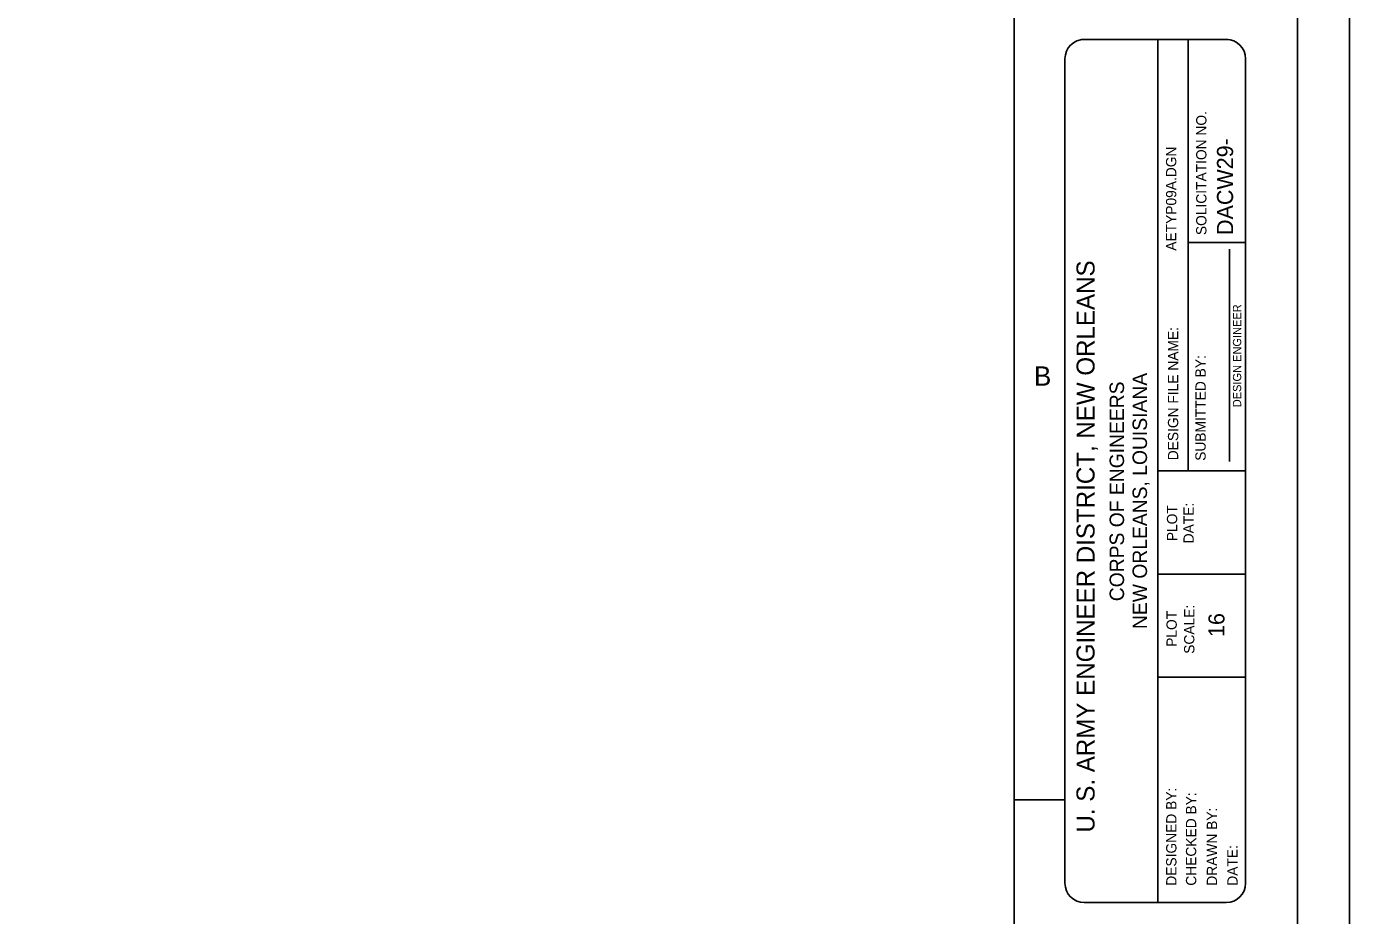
# Model space of a CAD drawing. Extents: x 22369.6 to 22428.3, y 22369.6 to 22415.
# Drawn here: x 22411.18 to 22428.29, y 22379.78 to 22391.29 of the extents above; entities that cross this region are included whole.
import ezdxf

# ---------------------------------------------------------------- set-up
doc = ezdxf.new("R2010")
doc.units = 0
for name, color, linetype in [('Level 1', 7, 'Continuous'), ('Level 10', 7, 'Continuous'), ('Level 2', 7, 'Continuous'), ('Level 7', 7, 'Continuous'), ('Level 9', 7, 'Continuous')]:
    doc.layers.add(name, color=color, linetype=linetype)

msp = doc.modelspace()

# ---------------------------------------------------------------- linework, layer by layer
at = {"layer": 'Level 1'}
for p, q in [((22426.72, 22391.12), (22424.816, 22391.12)), ((22425.808, 22391.12), (22425.808, 22379.952))]:
    msp.add_line(p, q, dxfattribs=at)
msp.add_lwpolyline([(22369.621, 22414.955), (22428.288, 22414.955), (22428.288, 22369.621), (22369.621, 22369.621)], close=True, dxfattribs=at)
for points in [[(22426.694, 22391.12), (22424.858, 22391.12)], [(22424.608, 22380.202), (22424.608, 22390.87)], [(22426.944, 22380.202), (22426.944, 22390.87)], [(22424.858, 22379.952), (22426.694, 22379.952)]]:
    msp.add_lwpolyline(points, dxfattribs=at)
for centre, start, end in [((22424.858, 22390.87), 90, 180), ((22426.694, 22390.87), 0, 90), ((22424.858, 22380.202), 180, 270), ((22426.694, 22380.202), 270, 0)]:
    msp.add_arc(centre, 0.25, start, end, dxfattribs=at)
at = {"layer": 'Level 10'}
msp.add_line((22423.952, 22381.28), (22424.608, 22381.28), dxfattribs=at)
at = {"layer": 'Level 2'}
for p, q in [((22426.202, 22391.12), (22426.202, 22385.536)), ((22426.944, 22388.491), (22426.202, 22388.491)), ((22426.736, 22385.657), (22426.736, 22388.405)), ((22426.944, 22385.536), (22425.808, 22385.536)), ((22426.944, 22384.203), (22425.808, 22384.203)), ((22426.944, 22382.869), (22425.808, 22382.869))]:
    msp.add_line(p, q, dxfattribs=at)
at = {"layer": 'Level 9'}
msp.add_line((22427.616, 22370.288), (22427.616, 22414.288), dxfattribs=at)
msp.add_lwpolyline([(22423.952, 22370.288), (22423.952, 22414.288)], dxfattribs=at)

# ---------------------------------------------------------------- texts
at = {"layer": 'Level 1'}
for s, height, p in [('SOLICITATION NO.', 0.13334, (22426.438, 22388.588)), ('AETYP09A.DGN', 0.13334, (22426.048, 22388.386)), ('U. S. ARMY ENGINEER DISTRICT, NEW ORLEANS', 0.23333, (22424.991, 22380.858)), ('DESIGN ENGINEER', 0.10666, (22426.887, 22386.361)), ('DESIGN FILE NAME:', 0.13334, (22426.073, 22385.675)), ('SUBMITTED BY:', 0.13334, (22426.428, 22385.668)), ('PLOT', 0.1333, (22426.06, 22384.628)), ('DATE:', 0.1333, (22426.273, 22384.6)), ('PLOT', 0.1333, (22426.054, 22383.261)), ('SCALE:', 0.1333, (22426.282, 22383.171)), ('DESIGNED BY:', 0.13334, (22426.05, 22380.17)), ('CHECKED BY:', 0.13334, (22426.306, 22380.17)), ('DRAWN BY:', 0.1333, (22426.575, 22380.17)), ('DATE:', 0.1333, (22426.841, 22380.17))]:
    msp.add_text(s, height=height, rotation=90, dxfattribs=at).set_placement(p)
msp.add_text('B', height=0.25, dxfattribs=at).set_placement((22424.208, 22386.64))
at = {"layer": 'Level 7'}
for s, height, p in [('DACW29-', 0.208, (22426.782, 22388.59)), ('NEW ORLEANS, LOUISIANA', 0.18667, (22425.669, 22383.491)), ('CORPS OF ENGINEERS', 0.18667, (22425.372, 22383.851)), ('16', 0.208, (22426.671, 22383.388))]:
    msp.add_text(s, height=height, rotation=90, dxfattribs=at).set_placement(p)

doc.saveas('drawing.dxf')
